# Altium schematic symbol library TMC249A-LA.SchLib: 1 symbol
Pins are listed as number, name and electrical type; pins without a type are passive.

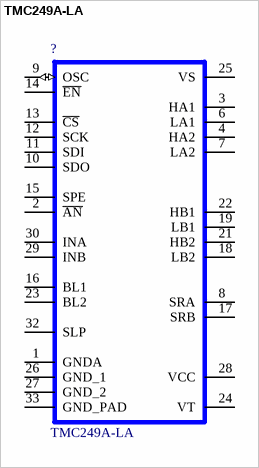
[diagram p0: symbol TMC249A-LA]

## TMC249A-LA
designator ?
High Current Microstep Stepper Motor Driver with sensorless stall detection, protection / diagnosis and SPI Interface, QFN32(7x7); Manufacturer: TRINAMIC; Geometry.Height: 1mm; Ordercode - Distri#1: 1460-1041-ND
footprint TMC_QFN32_0.65_7.0X7.0
pins: 1 GNDA, 2 ~{AN}, 3 HA1, 4 HA2, 6 LA1, 7 LA2, 8 SRA, 9 OSC (io), 10 SDO, 11 SDI, 12 SCK, 13 ~{CS}, 14 ~{EN}, 15 SPE, 16 BL1, 17 SRB, 18 LB2, 19 LB1, 21 HB2, 22 HB1, 23 BL2, 24 VT (power), 25 VS (power), 26 GND_1, 27 GND_2, 28 VCC (power), 29 INB, 30 INA, 32 SLP, 33 GND_PAD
